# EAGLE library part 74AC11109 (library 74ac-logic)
Dual J-K positive edge triggered FLIP FLOP
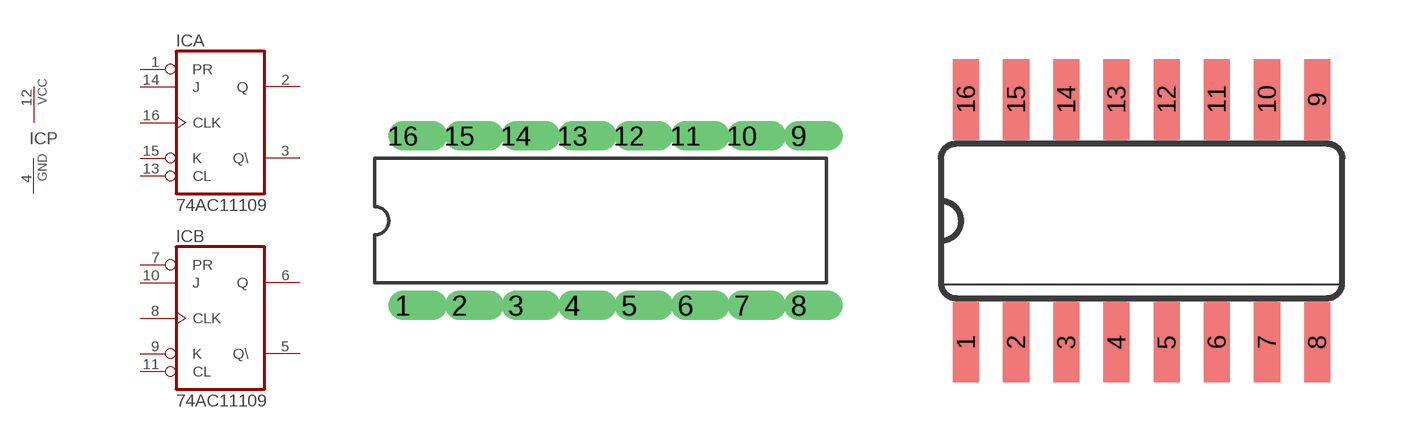
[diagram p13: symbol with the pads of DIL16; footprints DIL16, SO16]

Designator prefix IC; gates A=7411109 B=7411109 P=PWRN

## 74AC11109  [DIL16]
1  A:PR  in
2  A:Q  out
3  A:Q\  out
4  P:GND  pwr
5  B:Q\  out
6  B:Q  out
7  B:PR  in
8  B:CLK  in
9  B:K  in
10  B:J  in
11  B:CL  in
12  P:VCC  pwr
13  A:CL  in
14  A:J  in
15  A:K  in
16  A:CLK  in

## 74AC11109D  [SO16]
Pads as for DIL16

## Footprint DIL16 (pad centres in mm)
Dual In Line
drill 0.813 offset: 1 -8.89,-3.81; 2 -6.35,-3.81; 3 -3.81,-3.81; 4 -1.27,-3.81; 5 1.27,-3.81; 6 3.81,-3.81; 7 6.35,-3.81; 8 8.89,-3.81; 9 8.89,3.81; 10 6.35,3.81; 11 3.81,3.81; 12 1.27,3.81; 13 -1.27,3.81; 14 -3.81,3.81; 15 -6.35,3.81; 16 -8.89,3.81

## Footprint SO16 (pad centres in mm)
Small Outline package 150 mil
smd 0.66 x 2.032: 1 -4.445,-3.073; 2 -3.175,-3.073; 3 -1.905,-3.073; 4 -0.635,-3.073; 5 0.635,-3.073; 6 1.905,-3.073; 7 3.175,-3.073; 8 4.445,-3.073; 9 4.445,3.073; 10 3.175,3.073; 11 1.905,3.073; 12 0.635,3.073; 13 -0.635,3.073; 14 -1.905,3.073; 15 -3.175,3.073; 16 -4.445,3.073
